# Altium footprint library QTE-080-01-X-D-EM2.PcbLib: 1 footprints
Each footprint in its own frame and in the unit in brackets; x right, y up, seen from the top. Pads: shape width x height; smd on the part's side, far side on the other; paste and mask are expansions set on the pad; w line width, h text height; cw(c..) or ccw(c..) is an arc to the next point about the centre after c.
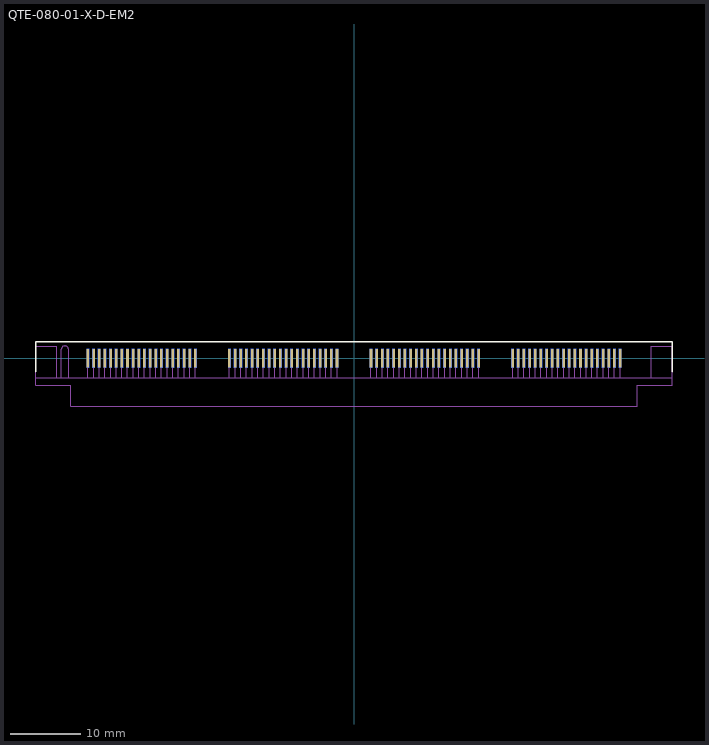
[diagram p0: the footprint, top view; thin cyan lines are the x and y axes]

## QTE-080-01-X-D-EM2 [mil] "0.80mm pitch, 160 pin, high speed terminal strip; w/edge mounts"
height 117.72
pads (160):
  rect 14.02x105 smd mask+0: 1(-1480.49,0) 3(-1449,0) 5(-1417.5,0) 7(-1386,0) 9(-1354.51,0) 11(-1323.01,0) 13(-1291.52,0) 15(-1260.02,0) 17(-1228.52,0) 19(-1197.03,0) 21(-1165.53,0) 23(-1134.04,0) 25(-1102.54,0) 27(-1071.04,0) 29(-1039.55,0) 31(-1008.05,0) 33(-976.56,0) 35(-945.06,0) 37(-913.56,0) 39(-882.07,0) 41(-692.97,0) 43(-661.48,0) 45(-629.98,0) 47(-598.48,0) 49(-566.99,0) 51(-535.49,0) 53(-504,0) 55(-472.5,0) 57(-441,0) 59(-409.51,0) 61(-378.01,0) 63(-346.52,0) 65(-315.02,0) 67(-283.52,0) 69(-252.03,0) 71(-220.53,0) 73(-189.04,0) 75(-157.54,0) 77(-126.04,0) 79(-94.55,0) 81(94.55,0) 83(126.04,0) 85(157.54,0) 87(189.04,0) 89(220.53,0) 91(252.03,0) 93(283.52,0) 95(315.02,0) 97(346.52,0) 99(378.01,0) 101(409.51,0) 103(441,0) 105(472.5,0) 107(504,0) 109(535.49,0) 111(566.99,0) 113(598.48,0) 115(629.98,0) 117(661.48,0) 119(692.97,0) 121(882.07,0) 123(913.56,0) 125(945.06,0) 127(976.56,0) 129(1008.05,0) 131(1039.55,0) 133(1071.04,0) 135(1102.54,0) 137(1134.04,0) 139(1165.53,0) 141(1197.03,0) 143(1228.52,0) 145(1260.02,0) 147(1291.52,0) 149(1323.01,0) 151(1354.51,0) 153(1386,0) 155(1417.5,0) 157(1449,0) 159(1480.49,0)
  rect 14.02x105 smd far side mask+0: 2(-1480.49,0) 4(-1449,0) 6(-1417.5,0) 8(-1386,0) 10(-1354.51,0) 12(-1323.01,0) 14(-1291.52,0) 16(-1260.02,0) 18(-1228.52,0) 20(-1197.03,0) 22(-1165.53,0) 24(-1134.04,0) 26(-1102.54,0) 28(-1071.04,0) 30(-1039.55,0) 32(-1008.05,0) 34(-976.56,0) 36(-945.06,0) 38(-913.56,0) 40(-882.07,0) 42(-692.97,0) 44(-661.48,0) 46(-629.98,0) 48(-598.48,0) 50(-566.99,0) 52(-535.49,0) 54(-504,0) 56(-472.5,0) 58(-441,0) 60(-409.51,0) 62(-378.01,0) 64(-346.52,0) 66(-315.02,0) 68(-283.52,0) 70(-252.03,0) 72(-220.53,0) 74(-189.04,0) 76(-157.54,0) 78(-126.04,0) 80(-94.55,0) 82(94.55,0) 84(126.04,0) 86(157.54,0) 88(189.04,0) 90(220.53,0) 92(252.03,0) 94(283.52,0) 96(315.02,0) 98(346.52,0) 100(378.01,0) 102(409.51,0) 104(441,0) 106(472.5,0) 108(504,0) 110(535.49,0) 112(566.99,0) 114(598.48,0) 116(629.98,0) 118(661.48,0) 120(692.97,0) 122(882.07,0) 124(913.56,0) 126(945.06,0) 128(976.56,0) 130(1008.05,0) 132(1039.55,0) 134(1071.04,0) 136(1102.54,0) 138(1134.04,0) 140(1165.53,0) 142(1197.03,0) 144(1228.52,0) 146(1260.02,0) 148(1291.52,0) 150(1323.01,0) 152(1354.51,0) 154(1386,0) 156(1417.5,0) 158(1449,0) 160(1480.49,0)
Top Overlay:
  lines w10: -1770.02,-74.61 -1770.02,92.52 1770.02,92.52 1770.02,-74.61
Top Solder:
  lines w5: -1480.49,0 -1480.49,52.48 ; -1449,0 -1449,52.48 ; -1417.5,0 -1417.5,52.48 ; -1386,0 -1386,52.48 ; -1354.51,0 -1354.51,52.48 ; -1323.01,0 -1323.01,52.48 ; -1291.52,0 -1291.52,52.48 ; -1260.02,0 -1260.02,52.48 ; -1228.52,0 -1228.52,52.48 ; -1197.03,0 -1197.03,52.48 ; -1165.53,0 -1165.53,52.48 ; -1134.04,0 -1134.04,52.48 ; -1102.54,0 -1102.54,52.48 ; -1071.04,0 -1071.04,52.48 ; -1039.55,0 -1039.55,52.48 ; -1008.05,0 -1008.05,52.48 ; -976.56,0 -976.56,52.48 ; -945.06,0 -945.06,52.48 ; -913.56,0 -913.56,52.48 ; -882.07,0 -882.07,52.48 ; -692.97,0 -692.97,52.48 ; -661.48,0 -661.48,52.48 ; -629.98,0 -629.98,52.48 ; -598.48,0 -598.48,52.48 ; -566.99,0 -566.99,52.48 ; -535.49,0 -535.49,52.48 ; -504,0 -504,52.48 ; -472.5,0 -472.5,52.48 ; -441,0 -441,52.48 ; -409.51,0 -409.51,52.48 ; -378.01,0 -378.01,52.48 ; -346.52,0 -346.52,52.48 ; -315.02,0 -315.02,52.48 ; -283.52,0 -283.52,52.48 ; -252.03,0 -252.03,52.48 ; -220.53,0 -220.53,52.48 ; -189.04,0 -189.04,52.48 ; -157.54,0 -157.54,52.48 ; -126.04,0 -126.04,52.48 ; -94.55,0 -94.55,52.48 ; 94.55,0 94.55,52.48 ; 126.04,0 126.04,52.48 ; 157.54,0 157.54,52.48 ; 189.04,0 189.04,52.48 ; 220.53,0 220.53,52.48 ; 252.03,0 252.03,52.48 ; 283.52,0 283.52,52.48 ; 315.02,0 315.02,52.48 ; 346.52,0 346.52,52.48 ; 378.01,0 378.01,52.48 ; 409.51,0 409.51,52.48 ; 441,0 441,52.48 ; 472.5,0 472.5,52.48 ; 504,0 504,52.48 ; 535.49,0 535.49,52.48 ; 566.99,0 566.99,52.48 ; 598.48,0 598.48,52.48 ; 629.98,0 629.98,52.48 ; 661.48,0 661.48,52.48 ; 692.97,0 692.97,52.48 ; 882.07,0 882.07,52.48 ; 913.56,0 913.56,52.48 ; 945.06,0 945.06,52.48 ; 976.56,0 976.56,52.48 ; 1008.05,0 1008.05,52.48 ; 1039.55,0 1039.55,52.48 ; 1071.04,0 1071.04,52.48 ; 1102.54,0 1102.54,52.48 ; 1134.04,0 1134.04,52.48 ; 1165.53,0 1165.53,52.48 ; 1197.03,0 1197.03,52.48 ; 1228.52,0 1228.52,52.48 ; 1260.02,0 1260.02,52.48 ; 1291.52,0 1291.52,52.48 ; 1323.01,0 1323.01,52.48 ; 1354.51,0 1354.51,52.48 ; 1386,0 1386,52.48 ; 1417.5,0 1417.5,52.48 ; 1449,0 1449,52.48 ; 1480.49,0 1480.49,52.48
Bottom Solder:
  lines w5: -1480.49,0 -1480.49,52.48 ; -1449,0 -1449,52.48 ; -1417.5,0 -1417.5,52.48 ; -1386,0 -1386,52.48 ; -1354.51,0 -1354.51,52.48 ; -1323.01,0 -1323.01,52.48 ; -1291.52,0 -1291.52,52.48 ; -1260.02,0 -1260.02,52.48 ; -1228.52,0 -1228.52,52.48 ; -1197.03,0 -1197.03,52.48 ; -1165.53,0 -1165.53,52.48 ; -1134.04,0 -1134.04,52.48 ; -1102.54,0 -1102.54,52.48 ; -1071.04,0 -1071.04,52.48 ; -1039.55,0 -1039.55,52.48 ; -1008.05,0 -1008.05,52.48 ; -976.56,0 -976.56,52.48 ; -945.06,0 -945.06,52.48 ; -913.56,0 -913.56,52.48 ; -882.07,0 -882.07,52.48 ; -692.97,0 -692.97,52.48 ; -661.48,0 -661.48,52.48 ; -629.98,0 -629.98,52.48 ; -598.48,0 -598.48,52.48 ; -566.99,0 -566.99,52.48 ; -535.49,0 -535.49,52.48 ; -504,0 -504,52.48 ; -472.5,0 -472.5,52.48 ; -441,0 -441,52.48 ; -409.51,0 -409.51,52.48 ; -378.01,0 -378.01,52.48 ; -346.52,0 -346.52,52.48 ; -315.02,0 -315.02,52.48 ; -283.52,0 -283.52,52.48 ; -252.03,0 -252.03,52.48 ; -220.53,0 -220.53,52.48 ; -189.04,0 -189.04,52.48 ; -157.54,0 -157.54,52.48 ; -126.04,0 -126.04,52.48 ; -94.55,0 -94.55,52.48 ; 94.55,0 94.55,52.48 ; 126.04,0 126.04,52.48 ; 157.54,0 157.54,52.48 ; 189.04,0 189.04,52.48 ; 220.53,0 220.53,52.48 ; 252.03,0 252.03,52.48 ; 283.52,0 283.52,52.48 ; 315.02,0 315.02,52.48 ; 346.52,0 346.52,52.48 ; 378.01,0 378.01,52.48 ; 409.51,0 409.51,52.48 ; 441,0 441,52.48 ; 472.5,0 472.5,52.48 ; 504,0 504,52.48 ; 535.49,0 535.49,52.48 ; 566.99,0 566.99,52.48 ; 598.48,0 598.48,52.48 ; 629.98,0 629.98,52.48 ; 661.48,0 661.48,52.48 ; 692.97,0 692.97,52.48 ; 882.07,0 882.07,52.48 ; 913.56,0 913.56,52.48 ; 945.06,0 945.06,52.48 ; 976.56,0 976.56,52.48 ; 1008.05,0 1008.05,52.48 ; 1039.55,0 1039.55,52.48 ; 1071.04,0 1071.04,52.48 ; 1102.54,0 1102.54,52.48 ; 1134.04,0 1134.04,52.48 ; 1165.53,0 1165.53,52.48 ; 1197.03,0 1197.03,52.48 ; 1228.52,0 1228.52,52.48 ; 1260.02,0 1260.02,52.48 ; 1291.52,0 1291.52,52.48 ; 1323.01,0 1323.01,52.48 ; 1354.51,0 1354.51,52.48 ; 1386,0 1386,52.48 ; 1417.5,0 1417.5,52.48 ; 1449,0 1449,52.48 ; 1480.49,0 1480.49,52.48
Mechanical 13:
  lines w3.94: -1653.72,-107.48 -1653.72,67.72 -1770.02,67.72 -1770.02,-107.48 ; -1628.05,-107.48 -1628.05,48.9 cw(c-1608.05,48.9) -1588.05,48.9 -1588.05,-107.48 ; -1480.49,-107.48 -1480.49,0 ; -1449,-107.48 -1449,0 ; -1417.5,-107.48 -1417.5,0 ; -1386,-107.48 -1386,0 ; -1354.51,-107.48 -1354.51,0 ; -1323.01,-107.48 -1323.01,0 ; -1291.52,-107.48 -1291.52,0 ; -1260.02,-107.48 -1260.02,0 ; -1228.52,-107.48 -1228.52,0 ; -1197.03,-107.48 -1197.03,0 ; -1165.53,-107.48 -1165.53,0 ; -1134.04,-107.48 -1134.04,0 ; -1102.54,-107.48 -1102.54,0 ; -1071.04,-107.48 -1071.04,0 ; -1039.55,-107.48 -1039.55,0 ; -1008.05,-107.48 -1008.05,0 ; -976.56,-107.48 -976.56,0 ; -945.06,-107.48 -945.06,0 ; -913.56,-107.48 -913.56,0 ; -882.07,-107.48 -882.07,0 ; -692.97,-107.48 -692.97,0 ; -661.48,-107.48 -661.48,0 ; -629.98,-107.48 -629.98,0 ; -598.48,-107.48 -598.48,0 ; -566.99,-107.48 -566.99,0 ; -535.49,-107.48 -535.49,0 ; -504,-107.48 -504,0 ; -472.5,-107.48 -472.5,0 ; -441,-107.48 -441,0 ; -409.51,-107.48 -409.51,0 ; -378.01,-107.48 -378.01,0 ; -346.52,-107.48 -346.52,0 ; -315.02,-107.48 -315.02,0 ; -283.52,-107.48 -283.52,0 ; -252.03,-107.48 -252.03,0 ; -220.53,-107.48 -220.53,0 ; -189.04,-107.48 -189.04,0 ; -157.54,-107.48 -157.54,0 ; -126.04,-107.48 -126.04,0 ; -94.55,-107.48 -94.55,0 ; 94.55,-107.48 94.55,0 ; 126.04,-107.48 126.04,0 ; 157.54,-107.48 157.54,0 ; 189.04,-107.48 189.04,0 ; 220.53,-107.48 220.53,0 ; 252.03,-107.48 252.03,0 ; 283.52,-107.48 283.52,0 ; 315.02,-107.48 315.02,0 ; 346.52,-107.48 346.52,0 ; 378.01,-107.48 378.01,0 ; 409.51,-107.48 409.51,0 ; 441,-107.48 441,0 ; 472.5,-107.48 472.5,0 ; 504,-107.48 504,0 ; 535.49,-107.48 535.49,0 ; 566.99,-107.48 566.99,0 ; 598.48,-107.48 598.48,0 ; 629.98,-107.48 629.98,0 ; 661.48,-107.48 661.48,0 ; 692.97,-107.48 692.97,0 ; 882.07,-107.48 882.07,0 ; 913.56,-107.48 913.56,0 ; 945.06,-107.48 945.06,0 ; 976.56,-107.48 976.56,0 ; 1008.05,-107.48 1008.05,0 ; 1039.55,-107.48 1039.55,0 ; 1071.04,-107.48 1071.04,0 ; 1102.54,-107.48 1102.54,0 ; 1134.04,-107.48 1134.04,0 ; 1165.53,-107.48 1165.53,0 ; 1197.03,-107.48 1197.03,0 ; 1228.52,-107.48 1228.52,0 ; 1260.02,-107.48 1260.02,0 ; 1291.52,-107.48 1291.52,0 ; 1323.01,-107.48 1323.01,0 ; 1354.51,-107.48 1354.51,0 ; 1386,-107.48 1386,0 ; 1417.5,-107.48 1417.5,0 ; 1449,-107.48 1449,0 ; 1480.49,-107.48 1480.49,0 ; 1653.72,-107.48 1653.72,67.72 1770.02,67.72 1770.02,-107.48 ; -1770.02,-107.48 1770.02,-107.48 ; -1770.02,-107.48 -1770.02,-150.79 -1575.02,-150.79 -1575.02,-267.32 1575.02,-267.32 1575.02,-150.79 1770.02,-150.79 1770.02,-107.48
  text ".Designator" at 0,0 h60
